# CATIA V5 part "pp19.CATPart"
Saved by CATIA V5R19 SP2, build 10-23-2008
Part number: pp19
Publications: "Line.1", "Point.2", "Plane.1", "Point.3", "Line.2"
Bounding box of the stored display mesh (mm): x 0 to 20, y -270 to 0, z 0 to 50
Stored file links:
  C:\Users\Welcome\Documents\thinkm2\pp19.CATPart
  C:\Users\Welcome\Documents\thinkm2\Brasmeca.CATProduct
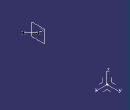
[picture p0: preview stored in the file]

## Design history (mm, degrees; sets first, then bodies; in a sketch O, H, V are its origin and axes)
AxisSystem1: origin (0, 0, 0), X (1, 0, 0), Y (0, 1, 0), Z (0, 0, 1)
Set1
  Point1: linked copy from another document
Body1 (main body)
  Line1: type PtDir, RefPoint Point1, Direction edge [XY plane of AxisSystem1 | ZX plane of AxisSystem1], Start 0, End 20
  Point2: type OnCurve, Support Line1, Length 15
  Plane1: type Normal, Curve Line1, RefPoint Point2
  Point3: (15, -270, 25), in AxisSystem1
  Line2: type PtPt, FirstPoint Point2, SecondPoint Point3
